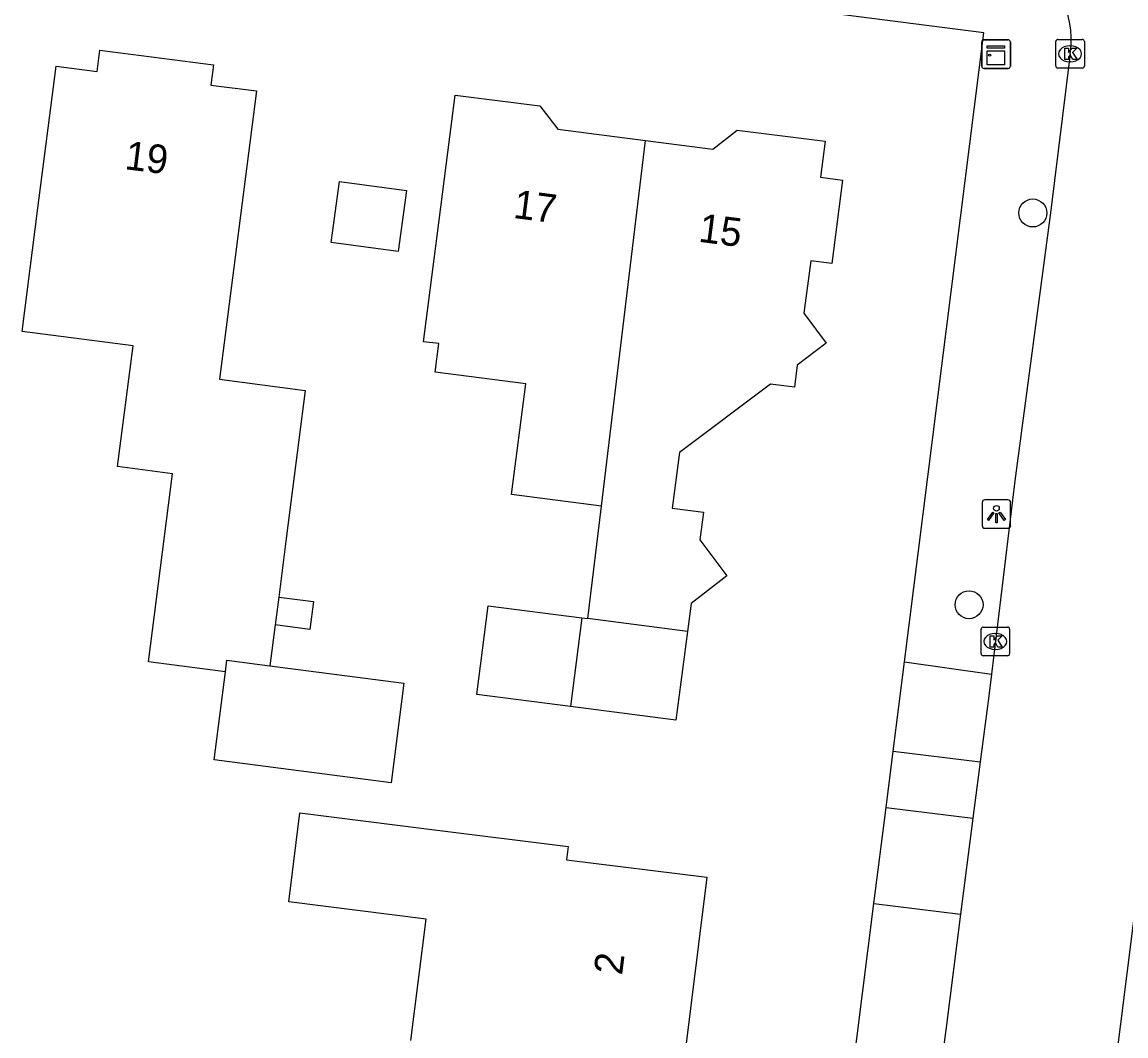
# Model space of a CAD drawing. Extents: x 161258 to 161838, y 380836 to 381727.
# Drawn here: x 161623.31 to 161661.92, y 381300.13 to 381335.59 of the extents above; entities that cross this region are included whole.
import ezdxf

# ---------------------------------------------------------------- set-up
doc = ezdxf.new("R2010")
doc.units = 0
for name, color, linetype in [('IMGEO_Boom', 7, 'Continuous'), ('IMGEO_Kast', 7, 'Continuous'), ('IMGEO_Kolk', 7, 'Continuous'), ('IMGEO_Lichtpunt', 7, 'Continuous'), ('IMGEO_Pand', 7, 'Continuous'), ('IMGEO_Pand_nummerreeks', 7, 'Continuous'), ('IMGEO_Rijbaan_lokaal_open', 7, 'Continuous'), ('IMGEO_Voetpad_open', 7, 'Continuous')]:
    doc.layers.add(name, color=color, linetype=linetype)

msp = doc.modelspace()

# ---------------------------------------------------------------- linework, layer by layer
at = {"layer": 'IMGEO_Boom'}
for centre in [(161658.667, 381328.909), (161656.437, 381315.208)]:
    msp.add_circle(centre, 0.489, dxfattribs=at)
at = {"layer": 'IMGEO_Kast'}
for p, q in [((161656.881, 381334.04), (161656.881, 381334.881)), ((161656.881, 381334.881), (161656.881, 381334.04)), ((161656.956, 381334.965), (161657.797, 381334.965)), ((161657.797, 381334.965), (161656.956, 381334.965)), ((161657.881, 381334.89), (161657.881, 381334.049)), ((161657.881, 381334.049), (161657.881, 381334.89)), ((161657.806, 381333.965), (161656.965, 381333.965)), ((161656.965, 381333.965), (161657.806, 381333.965))]:
    msp.add_line(p, q, dxfattribs=at)
for points in [[(161657.076, 381334.755), (161657.676, 381334.755), (161657.676, 381334.67), (161657.076, 381334.67), (161657.076, 381334.755)], [(161657.076, 381334.58), (161657.676, 381334.58), (161657.676, 381334.091), (161657.076, 381334.091), (161657.076, 381334.58)]]:
    msp.add_lwpolyline(points, dxfattribs=at)
msp.add_circle((161657.16, 381334.429), 0.0377, dxfattribs=at)
for centre, start, end in [((161656.959, 381334.887), 92.4484, 184.2845), ((161656.959, 381334.887), 92.4484, 184.2845), ((161657.803, 381334.887), 2.4484, 94.2845), ((161657.803, 381334.887), 2.4484, 94.2845), ((161656.959, 381334.043), 182.4484, 274.2845), ((161656.959, 381334.043), 182.4484, 274.2845), ((161657.803, 381334.043), 272.4484, 4.2845), ((161657.803, 381334.043), 272.4484, 4.2845)]:
    msp.add_arc(centre, 0.0779, start, end, dxfattribs=at)
at = {"layer": 'IMGEO_Kolk'}
for p, q in [((161659.469, 381334.051), (161659.469, 381334.903)), ((161659.544, 381334.977), (161660.396, 381334.977)), ((161659.957, 381334.757), (161659.982, 381334.757)), ((161660.47, 381334.903), (161660.47, 381334.051)), ((161660.396, 381333.977), (161659.544, 381333.977)), ((161659.98, 381334.197), (161659.955, 381334.197)), ((161656.855, 381313.498), (161656.855, 381314.35)), ((161656.93, 381314.424), (161657.782, 381314.424)), ((161657.856, 381314.35), (161657.856, 381313.498)), ((161657.343, 381314.204), (161657.368, 381314.204)), ((161657.366, 381313.644), (161657.341, 381313.644)), ((161657.782, 381313.424), (161656.93, 381313.424))]:
    msp.add_line(p, q, dxfattribs=at)
for points in [[(161659.469, 381334.051), (161659.469, 381334.903)], [(161659.544, 381334.977), (161660.396, 381334.977)], [(161660.47, 381334.903), (161660.47, 381334.051)], [(161659.79, 381334.677), (161659.913, 381334.677), (161659.913, 381334.526), (161660.043, 381334.677), (161660.207, 381334.677), (161660.061, 381334.526), (161660.214, 381334.277), (161660.062, 381334.277), (161659.977, 381334.441), (161659.913, 381334.374), (161659.913, 381334.277), (161659.79, 381334.277), (161659.79, 381334.677)], [(161660.396, 381333.977), (161659.544, 381333.977)], [(161656.855, 381313.498), (161656.855, 381314.35)], [(161656.93, 381314.424), (161657.782, 381314.424)], [(161657.856, 381314.35), (161657.856, 381313.498)], [(161657.176, 381314.124), (161657.299, 381314.124), (161657.299, 381313.973), (161657.429, 381314.124), (161657.593, 381314.124), (161657.447, 381313.973), (161657.6, 381313.724), (161657.448, 381313.724), (161657.363, 381313.888), (161657.299, 381313.821), (161657.299, 381313.724), (161657.176, 381313.724), (161657.176, 381314.124)], [(161657.782, 381313.424), (161656.93, 381313.424)]]:
    msp.add_lwpolyline(points, dxfattribs=at)
for centre, start, end in [((161659.546, 381334.901), 91.552, 178.448), ((161659.546, 381334.901), 91.552, 178.448), ((161660.394, 381334.901), 1.552, 88.448), ((161660.394, 381334.901), 1.552, 88.448), ((161659.546, 381334.053), 181.552, 268.448), ((161659.546, 381334.053), 181.552, 268.448), ((161660.394, 381334.053), 271.552, 358.448), ((161660.394, 381334.053), 271.552, 358.448), ((161656.932, 381314.348), 91.552, 178.448), ((161656.932, 381314.348), 91.552, 178.448), ((161657.78, 381314.348), 1.552, 88.448), ((161657.78, 381314.348), 1.552, 88.448), ((161656.932, 381313.5), 181.552, 268.448), ((161656.932, 381313.5), 181.552, 268.448), ((161657.78, 381313.5), 271.552, 358.448), ((161657.78, 381313.5), 271.552, 358.448)]:
    msp.add_arc(centre, 0.0765, start, end, dxfattribs=at)
for centre, major_axis, ratio, start_param, end_param in [((161659.956, 381334.477), (-0.387, 0.002), 0.722429, 4.712389, 7.853982), ((161659.981, 381334.477), (-0.39, 0.002), 0.717154, 1.570796, 4.712389), ((161657.342, 381313.924), (-0.387, 0.002), 0.722429, 4.712389, 7.853982), ((161657.367, 381313.924), (-0.39, 0.002), 0.717154, 1.570796, 4.712389)]:
    msp.add_ellipse(centre, major_axis=major_axis, ratio=ratio, start_param=start_param, end_param=end_param, dxfattribs=at)
at = {"layer": 'IMGEO_Lichtpunt'}
for p, q in [((161657.798, 381318.877), (161656.99, 381318.877)), ((161657.798, 381318.877), (161656.99, 381318.877)), ((161656.896, 381318.782), (161656.896, 381317.975)), ((161656.896, 381318.782), (161656.896, 381317.975)), ((161657.892, 381317.975), (161657.892, 381318.782)), ((161657.892, 381317.975), (161657.892, 381318.782)), ((161656.99, 381317.881), (161657.798, 381317.881)), ((161656.99, 381317.881), (161657.798, 381317.881))]:
    msp.add_line(p, q, dxfattribs=at)
for points in [[(161657.27, 381318.446), (161657.309, 381318.418), (161657.121, 381318.156), (161657.083, 381318.183), (161657.27, 381318.446)], [(161657.372, 381318.398), (161657.419, 381318.398), (161657.419, 381318.076), (161657.372, 381318.076), (161657.372, 381318.398)], [(161657.482, 381318.418), (161657.52, 381318.445), (161657.707, 381318.183), (161657.668, 381318.155), (161657.482, 381318.418)]]:
    msp.add_lwpolyline(points, dxfattribs=at)
msp.add_circle((161657.395, 381318.58), 0.0994, dxfattribs=at)
for centre, start, end in [((161656.99, 381318.782), 90, 180), ((161656.99, 381318.782), 90, 180), ((161657.798, 381318.782), 0, 90), ((161657.798, 381318.782), 0, 90), ((161656.99, 381317.975), 180, 270), ((161656.99, 381317.975), 180, 270), ((161657.798, 381317.975), 270, 0), ((161657.798, 381317.975), 270, 360)]:
    msp.add_arc(centre, 0.0946, start, end, dxfattribs=at)
at = {"layer": 'IMGEO_Pand'}
for points in [[(161630.42, 381312.863), (161627.73, 381313.21), (161628.574, 381319.791), (161626.648, 381320.039), (161627.191, 381324.268), (161623.307, 381324.767), (161623.861, 381329.081), (161624.498, 381334.04), (161625.934, 381333.853), (161626.03, 381334.6), (161630, 381334.09), (161629.909, 381333.382), (161631.507, 381333.177), (161630.211, 381323.091), (161633.216, 381322.705), (161632.551, 381317.528), (161632.287, 381315.473)], [(161643.574, 381318.66), (161640.428, 381319.065), (161640.925, 381322.933), (161637.758, 381323.34), (161637.887, 381324.339), (161637.352, 381324.408), (161637.827, 381328.105), (161638.46, 381333.031), (161641.425, 381332.651), (161642.05, 381331.841), (161645.116, 381331.447)], [(161645.116, 381331.447), (161647.468, 381331.145), (161648.328, 381331.81), (161651.406, 381331.415), (161651.245, 381330.159), (161652.011, 381330.061), (161651.636, 381327.143), (161650.896, 381327.238), (161650.661, 381325.404), (161651.434, 381324.357), (161650.427, 381323.589), (161650.328, 381322.815), (161649.485, 381322.924), (161646.305, 381320.53), (161646.055, 381318.586), (161647.146, 381318.446), (161647.017, 381317.475), (161647.96, 381316.22), (161646.72, 381315.255), (161646.589, 381314.273)], [(161643.574, 381318.66), (161645.116, 381331.447)], [(161634.118, 381327.882), (161634.408, 381330.013), (161636.761, 381329.693), (161636.47, 381327.561), (161634.118, 381327.882)], [(161643.099, 381314.721), (161643.574, 381318.66)], [(161632.287, 381315.473), (161633.497, 381315.317), (161633.372, 381314.345), (161632.162, 381314.5)], [(161632.287, 381315.473), (161632.162, 381314.5)], [(161642.488, 381311.649), (161639.214, 381312.07), (161639.612, 381315.17), (161642.886, 381314.748)], [(161642.886, 381314.748), (161642.488, 381311.649)], [(161642.886, 381314.748), (161643.099, 381314.721)], [(161646.589, 381314.273), (161643.099, 381314.721)], [(161632.162, 381314.5), (161631.979, 381313.072)], [(161646.589, 381314.273), (161646.176, 381311.175), (161642.488, 381311.649)], [(161631.979, 381313.072), (161636.666, 381312.469), (161636.217, 381308.981), (161630.024, 381309.778), (161630.42, 381312.863)], [(161630.42, 381312.863), (161630.472, 381313.266), (161631.979, 381313.072)], [(161636.91, 381299.963), (161637.44, 381304.215), (161632.639, 381304.812), (161633.024, 381307.926), (161637.455, 381307.374), (161642.416, 381306.757), (161642.357, 381306.285), (161647.264, 381305.674), (161646.401, 381298.742)]]:
    msp.add_lwpolyline(points, dxfattribs=at)
at = {"layer": 'IMGEO_Rijbaan_lokaal_open'}
for points in [[(161659.97, 381334.473), (161659.281, 381328.911), (161658.036, 381319.535), (161657.217, 381312.776)], [(161657.217, 381312.776), (161657.114, 381311.926), (161656.827, 381309.714)], [(161656.827, 381309.714), (161656.572, 381307.747)], [(161656.572, 381307.747), (161656.137, 381304.387)], [(161659.96, 381287.198), (161661.538, 381298.881), (161662.388, 381305.648)], [(161656.137, 381304.387), (161655.635, 381300.426), (161654.545, 381292.14), (161654.389, 381290.926)]]:
    msp.add_lwpolyline(points, dxfattribs=at)
msp.add_arc((161656.76, 381334.983), 3.251, 350.9695, 68.8021, dxfattribs=at)
at = {"layer": 'IMGEO_Voetpad_open'}
for points in [[(161654.173, 381313.208), (161656.956, 381335.212), (161638.457, 381337.583)], [(161653.779, 381310.086), (161654.173, 381313.208)], [(161654.173, 381313.208), (161657.217, 381312.776)], [(161653.531, 381308.117), (161653.779, 381310.086)], [(161653.779, 381310.086), (161656.827, 381309.714)], [(161653.107, 381304.757), (161653.531, 381308.117)], [(161653.531, 381308.117), (161656.572, 381307.747)], [(161651.304, 381290.495), (161653.107, 381304.757)], [(161653.107, 381304.757), (161656.137, 381304.387)]]:
    msp.add_lwpolyline(points, dxfattribs=at)

# ---------------------------------------------------------------- texts
at = {"layer": 'IMGEO_Pand_nummerreeks'}
for s, rotation, p in [('19', 352.9813, (161626.872, 381330.444)), ('17', 352.6776, (161640.462, 381328.738)), ('15', 352.6776, (161646.944, 381327.906)), ('2', 82.9043, (161644.296, 381302.228))]:
    msp.add_text(s, height=1, rotation=rotation, dxfattribs=at).set_placement(p)

doc.saveas('drawing.dxf')
